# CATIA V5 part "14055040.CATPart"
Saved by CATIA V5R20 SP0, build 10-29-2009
Part number: 14055040
Definition: NONE
Nomenclature: 14055040
Source: Unknown
Description: 14055040
Bounding box of the stored display mesh (mm): x -20 to 80, y -41.5 to 31.6, z -31.6 to 31.6
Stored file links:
  C:\Users\Utente\Desktop\IO LAVORO\3D X SITO CF\X SITO\PLASTICA\RF2\14055040.CATPart
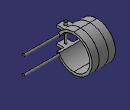
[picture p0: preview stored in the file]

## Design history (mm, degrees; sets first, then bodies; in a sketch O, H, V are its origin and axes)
Body1 "14055040" (main body)
  Solid1: solid without history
